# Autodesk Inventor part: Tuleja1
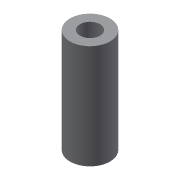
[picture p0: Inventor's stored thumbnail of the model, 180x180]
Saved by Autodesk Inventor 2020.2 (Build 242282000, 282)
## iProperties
Created: 2005-10
Part Number: Tuleja1
Document SubType Name: Modeling
Designer: F.Stasiak
Density: 1 g/cm^3
Material: Ogólny
Appearance: Domyślna
Manager: www.cadconsulting.pl
Company: Fabian Stasiak CAD Consulting
Author: F.Stasiak
Subject: Zbiór ćwiczeń. Autodesk Inventor 2020. Kurs podstawowy
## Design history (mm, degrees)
sketch "Szkic1"
  geometry: C1 r 50 at (0, 0); C2 r 25 at (0, 0); 1 further point
  constraints: 2 centre point, 2 coincident
  dimensions: "d0" = 100 diameter of C1; "d1" = 50 diameter of C2
extrude "Wyciągnięcie proste1" new body sketch "Szkic1" distance "d2" = 260; taper "d3" = 0 deg
node "Bryła1"
node "Korpusy bryłowe"
node "Korpusy powierzchniowe"
